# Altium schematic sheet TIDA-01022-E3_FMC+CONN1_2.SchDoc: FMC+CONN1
size 431 x 279 mm; Date: Not shown in title block; ApprovedBy: Not shown in title block; CheckedBy: Not shown in title block; Author: Not shown in title block; CompanyName: Not shown in title block; DrawnBy: Avinash N; Engineer: Not shown in title block; Organization: Not shown in title block; Address1: Not shown in title block; Address2: Not shown in title block; Address3: Not shown in title block; Address4: Not shown in title block; DocumentNumber: 1; Revision: Use project parameter SCH_Rev; SheetNumber: 18; SheetTotal: 26; PageSetup: Record=PageOptions¦CenterHorizontal=True¦CenterVertical=True¦PrintScale=1.00¦XCorrection=1.00¦YCorrection=1.00¦PrintKind=0¦BorderSize=5000000¦LeftOffset=0¦BottomOffset=0¦Orientation=2¦PaperLength=1000¦PaperWidth=1000¦Scale=100¦PaperSource=15¦PrintQuality=600¦MediaType=1¦DitherType=10¦PaperKind=Letter¦PrintScaleMode=1
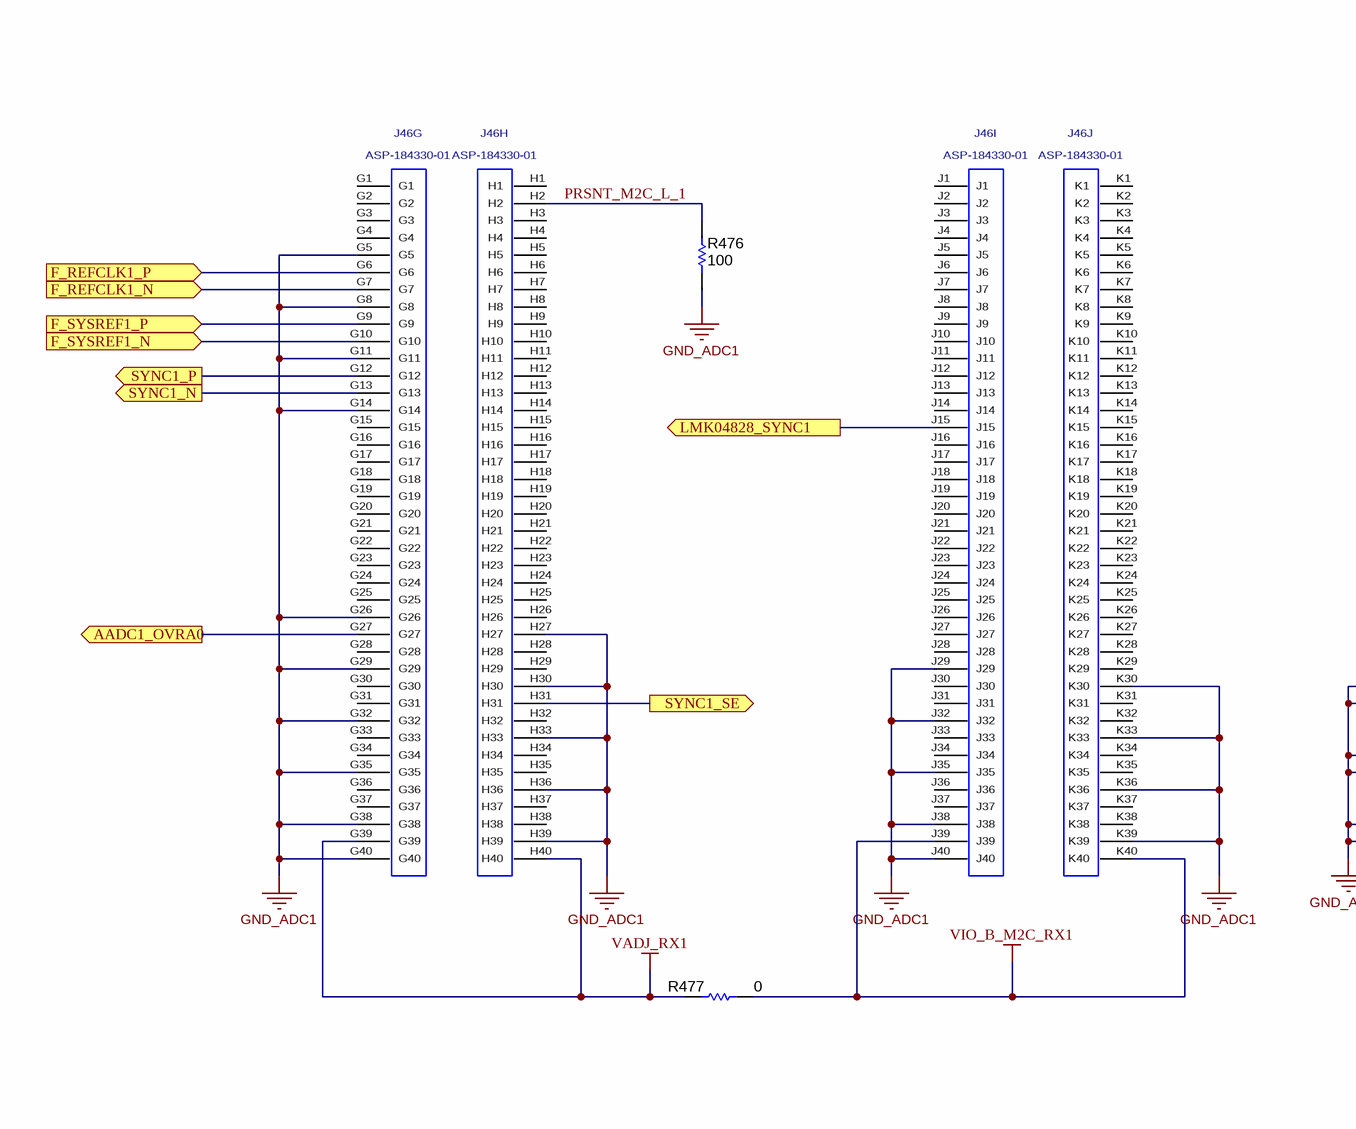
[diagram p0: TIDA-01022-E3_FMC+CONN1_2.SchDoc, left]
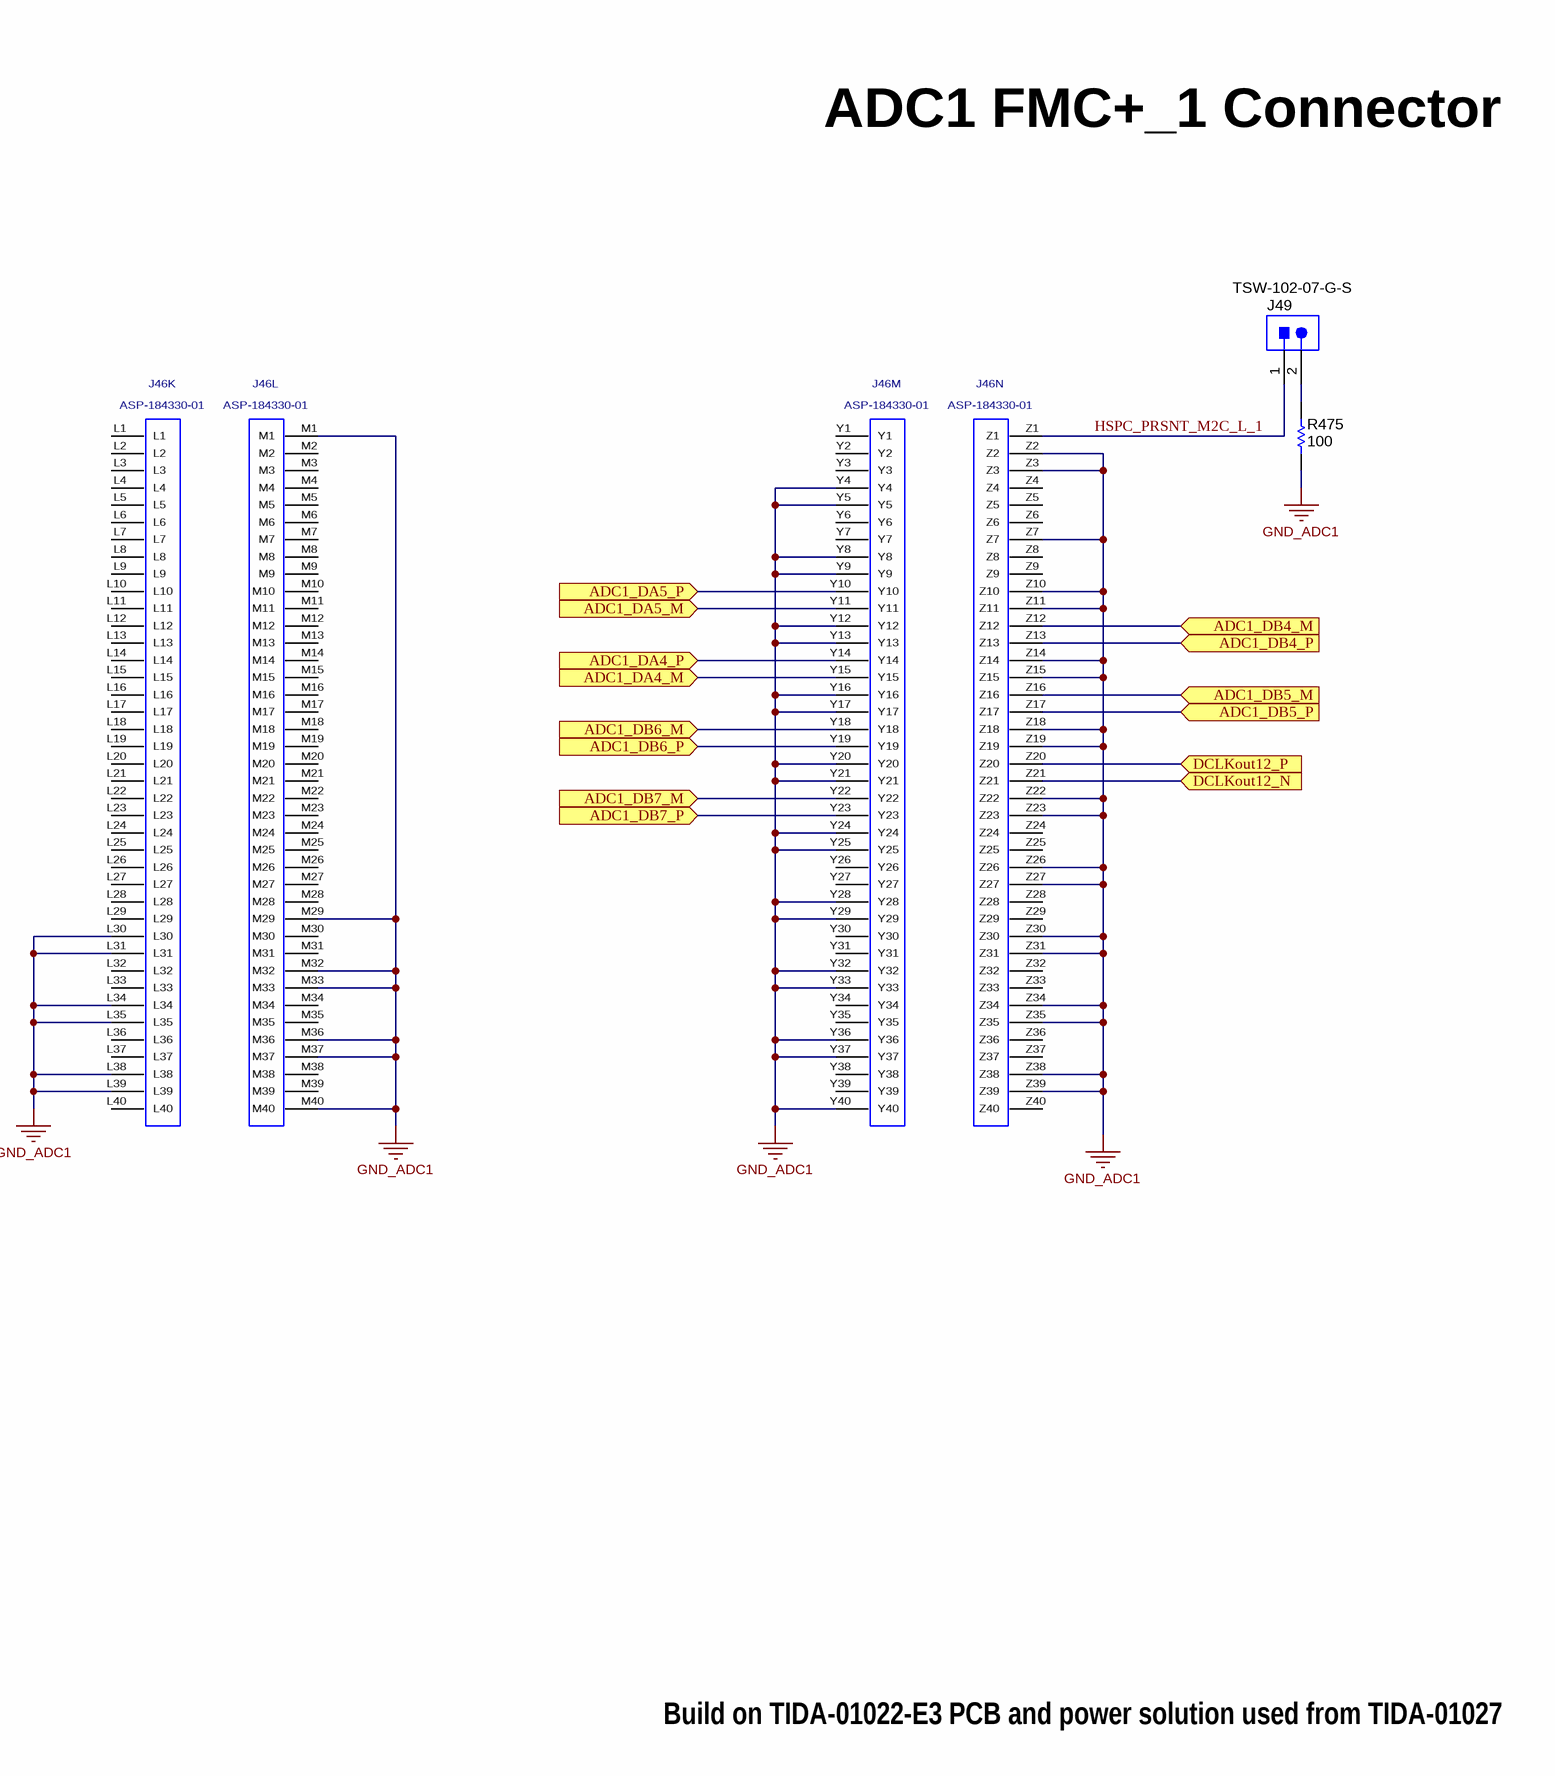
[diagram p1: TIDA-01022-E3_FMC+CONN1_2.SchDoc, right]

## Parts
J46  ASP-184330-01  [ASP-184330-01]  (parts G,H,I,J,K,L,M,N of 14)
J49  TSW-102-07-G-S  [TSW-102-07-G-S]
R475  ValueDisplayed: 100  [0402]  (hidden comment: CRCW0402100RJNED)
R476  ValueDisplayed: 100  [0402]  (hidden comment: CRCW0402100RJNED)
R477  ValueDisplayed: 0  [0402]  (hidden comment: CRCW04020000Z0ED)

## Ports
AADC1_OVRA0 (out), ADC1_DA4_M (in), ADC1_DA4_P (in), ADC1_DA5_M (in), ADC1_DA5_P (in), ADC1_DB4_M (in), ADC1_DB4_P (in), ADC1_DB5_M (in), ADC1_DB5_P (in), ADC1_DB6_M (in), ADC1_DB6_P (in), ADC1_DB7_M (in), ADC1_DB7_P (in), DCLKout12_N (in), DCLKout12_P (in), F_REFCLK1_N (in), F_REFCLK1_P (in), F_SYSREF1_N (in), F_SYSREF1_P (in), LMK04828_SYNC1 (out), SYNC1_N (out), SYNC1_P (out), SYNC1_SE (out)

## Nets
GND_ADC1: J46.G5 J46.G8 J46.G11 J46.G14 J46.G26 J46.G29 J46.G32 J46.G35 J46.G38 J46.G40 J46.H27 J46.H30 J46.H33 J46.H36 J46.H39 J46.J29 J46.J32 J46.J35 J46.J38 J46.J40 J46.K30 J46.K33 J46.K36 J46.K39 J46.L30 J46.L31 J46.L34 J46.L35 J46.L38 J46.L39 J46.M1 J46.M29 J46.M32 J46.M33 J46.M36 J46.M37 J46.M40 J46.Y4 J46.Y5 J46.Y8 J46.Y9 J46.Y12 J46.Y13 J46.Y16 J46.Y17 J46.Y20 J46.Y21 J46.Y24 J46.Y25 J46.Y28 J46.Y29 J46.Y32 J46.Y33 J46.Y36 J46.Y37 J46.Y40 J46.Z2 J46.Z3 J46.Z7 J46.Z10 J46.Z11 J46.Z14 J46.Z15 J46.Z18 J46.Z19 J46.Z22 J46.Z23 J46.Z26 J46.Z27 J46.Z30 J46.Z31 J46.Z34 J46.Z35 J46.Z38 J46.Z39 R475.1 R476.1
VADJ_RX1: J46.G39 J46.H40 R477.2
VIO_B_M2C_RX1: J46.J39 J46.K40 R477.1
AADC1_OVRA0: J46.G27 ; port AADC1_OVRA0
ADC1_DA4_M: J46.Y15 ; port ADC1_DA4_M
ADC1_DA4_P: J46.Y14 ; port ADC1_DA4_P
ADC1_DA5_M: J46.Y11 ; port ADC1_DA5_M
ADC1_DA5_P: J46.Y10 ; port ADC1_DA5_P
ADC1_DB4_M: J46.Z12 ; port ADC1_DB4_M
ADC1_DB4_P: J46.Z13 ; port ADC1_DB4_P
ADC1_DB5_M: J46.Z16 ; port ADC1_DB5_M
ADC1_DB5_P: J46.Z17 ; port ADC1_DB5_P
ADC1_DB6_M: J46.Y18 ; port ADC1_DB6_M
ADC1_DB6_P: J46.Y19 ; port ADC1_DB6_P
ADC1_DB7_M: J46.Y22 ; port ADC1_DB7_M
ADC1_DB7_P: J46.Y23 ; port ADC1_DB7_P
DCLKout12_N: J46.Z21 ; port DCLKout12_N
DCLKout12_P: J46.Z20 ; port DCLKout12_P
F_REFCLK1_N: J46.G7 ; port F_REFCLK1_N
F_REFCLK1_P: J46.G6 ; port F_REFCLK1_P
F_SYSREF1_N: J46.G10 ; port F_SYSREF1_N
F_SYSREF1_P: J46.G9 ; port F_SYSREF1_P
HSPC_PRSNT_M2C_L_1: J46.Z1 J49.1
LMK04828_SYNC1: J46.J15 ; port LMK04828_SYNC1
PRSNT_M2C_L_1: J46.H2 R476.2
SYNC1_N: J46.G13 ; port SYNC1_N
SYNC1_P: J46.G12 ; port SYNC1_P
SYNC1_SE: J46.H31 ; port SYNC1_SE
NetJ49_2: J49.2 R475.2

Not connected (* = marked no-connect by the designer): J46 G1 G2 G3 G4 G15 G16 G17 G18 G19 G20 G21 G22 G23 G24 G25 G28 G30 G31 G33 G34 G36 G37 H1 H3 H4 H5 H6 H7 H8 H9 H10 H11 H12 H13 H14 H15 H16 H17 H18 H19 H20 H21 H22 H23 H24 H25 H26 H28 H29 H32 H34 H35 H37 H38 J1 J2 J3 J4 J5 J6 J7 J8 J9 J10 J11 J12 J13 J14 J16 J17 J18 J19 J20 J21 J22 J23 J24 J25 J26 J27 J28 J30 J31 J33 J34 J36 J37 K1 K2 K3 K4 K5 K6 K7 K8 K9 K10 K11 K12 K13 K14 K15 K16 K17 K18 K19 K20 K21 K22 K23 K24 K25 K26 K27 K28 K29 K31 K32 K34 K35 K37 K38 L1 L2 L3 L4 L5 L6 L7 L8 L9 L10 L11 L12 L13 L14 L15 L16 L17 L18 L19 L20 L21 L22 L23 L24 L25 L26 L27 L28 L29 L32 L33 L36 L37 L40 M2 M3 M4 M5 M6 M7 M8 M9 M10 M11 M12 M13 M14 M15 M16 M17 M18 M19 M20 M21 M22 M23 M24 M25 M26 M27 M28 M30 M31 M34 M35 M38 M39 Y1 Y2 Y3 Y6 Y7 Y26 Y27 Y30 Y31 Y34 Y35 Y38 Y39 Z4 Z5 Z6 Z8 Z9 Z24 Z25 Z28 Z29 Z32 Z33 Z36 Z37 Z40

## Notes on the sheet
- ADC1 FMC+_1 Connector
- Build on TIDA-01022-E3 PCB and power solution used from TIDA-01027

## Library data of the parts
J46 = ASP-184330-01: 14 ROW .050 PITCH TERMINAL ARRAY ASM.; Manufacturer: SAMTEC
J49 = TSW-102-07-G-S: Header, 100mil, 2x1, Gold, TH; Manufacturer: Samtec; SymbolCreator: a0412235; Pitch_mm: 2.54; Gender: Male; Shrouded: N; Row_Count: 1; Current_A: 6.3; Voltage_V: 550; Cert_CSA: Y
R475 R476 = CRCW0402100RJNED: RES, 100, 5%, 0.063 W, 0402; Manufacturer: Vishay-Dale; CompType: Resistor; Value: 100; Value_Code: 100R; Tolerance_%: 5; Power_W: 0.063; Value2: 0.063W; VDC_V: 50; TempCo: 200 ppm/C; SizeArea_mm2: 0.5; SizeX_mm: 1; SizeZ_mm: 0.6; EIA_Code: E24; U/M: EA; AEC Category: Q200
R477 = CRCW04020000Z0ED: RES, 0, 5%, 0.063 W, 0402; Manufacturer: Vishay-Dale; CompType: Resistor; Value: 0; Value_Code: 0000; Tolerance_%: 5; Power_W: 0.063; Value2: 0.063W; VDC_V: 50; TempCo: 200 ppm/C; SizeArea_mm2: 0.5; SizeX_mm: 1; SizeZ_mm: 0.6; EIA_Code: E24; U/M: EA; AEC Category: Q200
